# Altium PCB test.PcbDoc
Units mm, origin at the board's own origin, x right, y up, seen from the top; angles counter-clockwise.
Board outline 37.73 x 68.07 mm, 2 copper layers (Top Layer, Bottom Layer); 30 components, 0 nets, 107 pads, 18 vias.
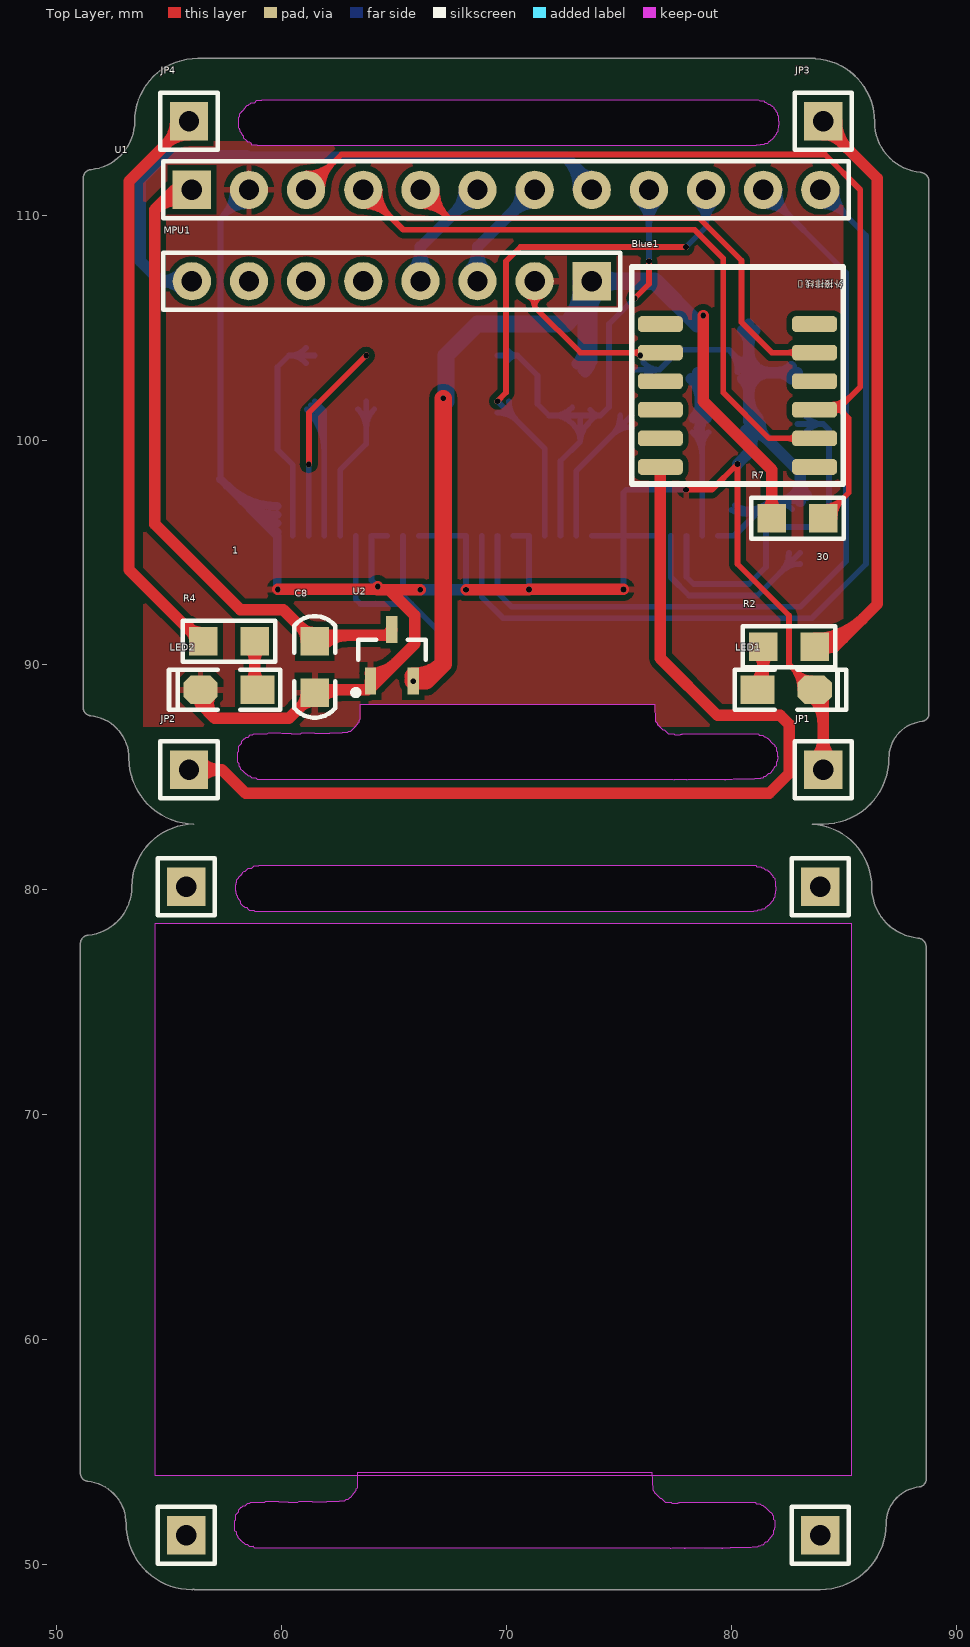
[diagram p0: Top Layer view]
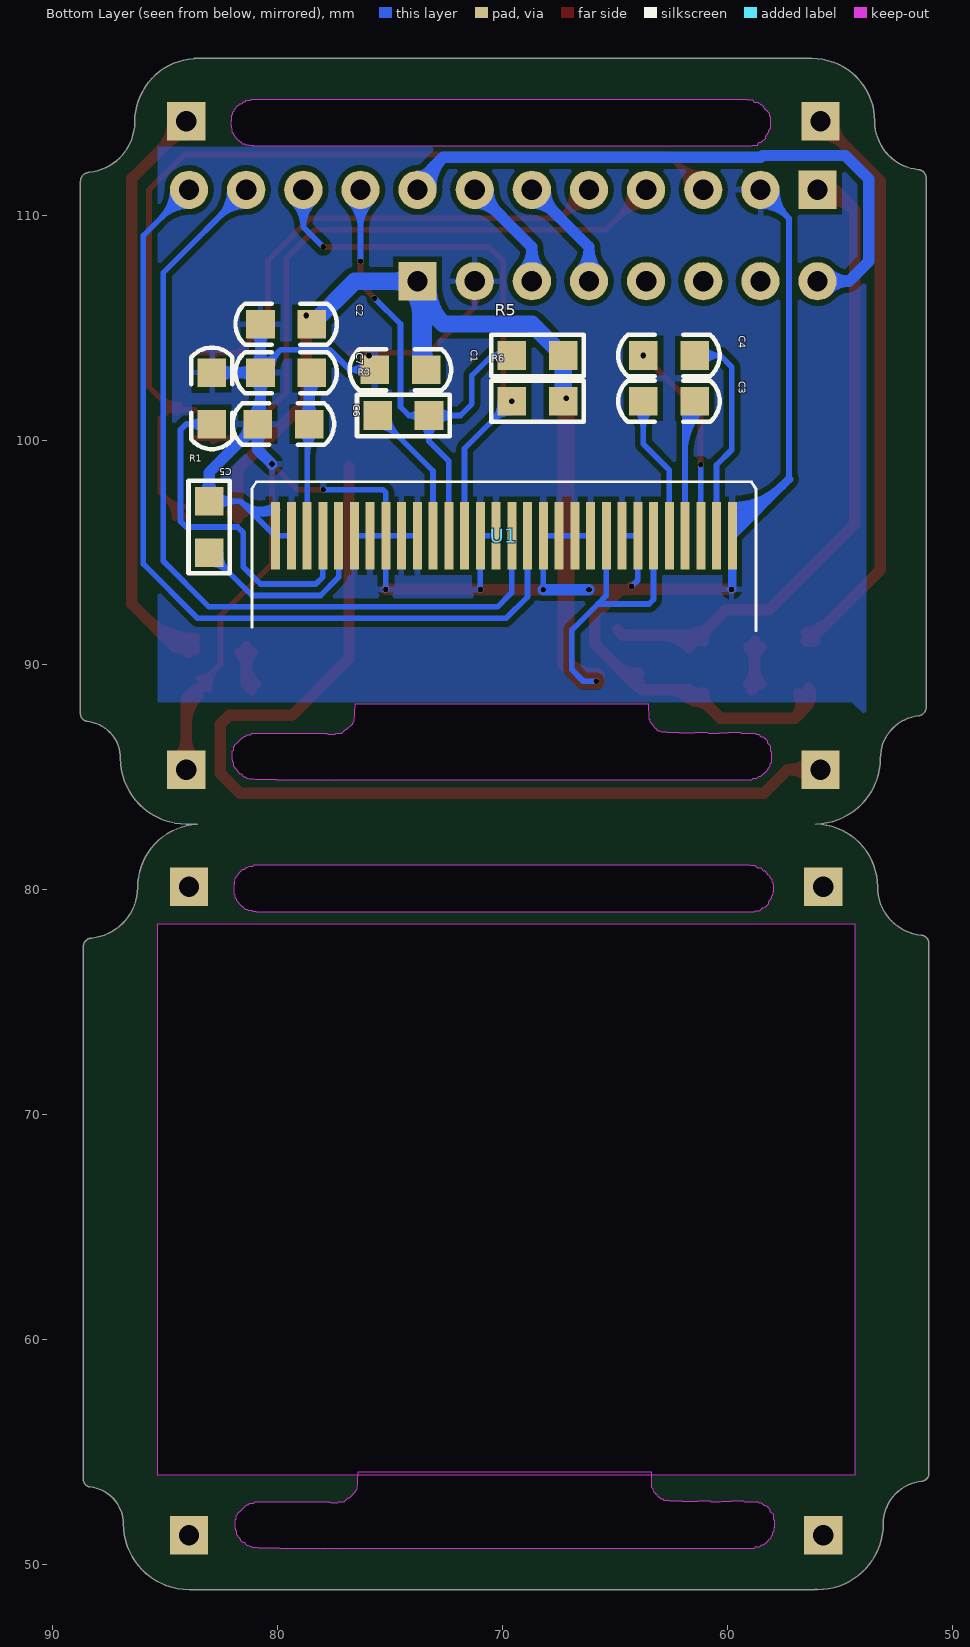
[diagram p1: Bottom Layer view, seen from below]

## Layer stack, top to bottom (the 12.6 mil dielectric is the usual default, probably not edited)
Top Solder: solder mask 0.0102, Solder Resist, Dk 3.5
Top Layer: signal copper 0.0356
Dielectric 1: dielectric 0.32, FR-4, Dk 4.8
Bottom Layer: signal copper 0.0356
Bottom Solder: solder mask 0.0102, Solder Resist, Dk 3.5

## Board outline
51.363,53.712 cw(c51.412,54.07) 51.054,54.11 51.054,77.592 cw(c51.426,77.617) 51.394,77.989 ccw(c51.181,80.137) 53.34,80.137 cw(c56.134,80.137) 56.087,82.931 cw(c56.134,85.852) 53.213,85.852 cw(c53.34,85.852) 53.213,85.853 cw(c51.308,85.852) 53.213,85.852 53.213,85.853 ccw(c51.308,85.852) 51.496,87.747 ccw(c51.308,85.852) 51.495,87.747 51.496,87.747 cw(c51.507,87.874) 51.49,87.748 cw(c51.539,88.106) 51.181,88.146 51.181,111.628 cw(c51.553,111.653) 51.521,112.025 ccw(c51.308,114.173) 53.467,114.173 cw(c56.261,114.173) 56.261,116.967 83.693,116.967 cw(c83.693,116.84) 83.732,116.961 cw(c83.545,114.152) 86.36,114.152 cw(c83.545,114.152) 86.36,114.131 cw(c88.625,114.152) 86.36,114.132 86.36,114.131 ccw(c88.625,114.152) 88.398,111.899 cw(c88.386,111.511) 88.773,111.511 cw(c88.386,111.511) 88.773,111.505 cw(c88.386,111.511) 88.773,111.504 88.773,111.506 88.773,87.895 cw(c88.428,87.84) 88.778,87.84 cw(c88.428,87.84) 88.497,87.497 cw(c88.472,87.621) 88.482,87.494 cw(c88.646,85.852) 88.484,87.495 88.482,87.494 ccw(c88.646,85.852) 86.995,85.852 cw(c84.074,85.852) 84.074,82.931 83.58,82.931 cw(c83.566,82.804) 83.605,82.925 cw(c83.418,80.116) 86.233,80.116 cw(c83.418,80.116) 86.233,80.095 cw(c88.498,80.116) 86.233,80.096 86.233,80.095 ccw(c88.498,80.116) 88.271,77.863 cw(c88.259,77.475) 88.646,77.475 cw(c88.259,77.475) 88.646,77.469 cw(c88.259,77.475) 88.646,77.468 88.646,77.47 88.646,53.859 cw(c88.301,53.804) 88.651,53.804 cw(c88.301,53.804) 88.37,53.461 cw(c88.345,53.585) 88.355,53.458 cw(c88.519,51.816) 88.357,53.459 88.355,53.458 ccw(c88.519,51.816) 86.868,51.816 cw(c83.947,51.816) 83.947,48.895 56.142,48.895 cw(c56.142,49.022) 56.074,48.914 cw(c56.007,49.022) 56.007,48.895 cw(c56.007,51.816) 53.086,51.816 cw(c53.213,51.816) 53.086,51.817 cw(c51.181,51.816) 53.086,51.816 53.086,51.817 ccw(c51.181,51.816) 51.369,53.711 cw(c51.38,53.838)
cut-out: 58.01,80.46 58.1,80.55 58.1,80.58 58.11,80.58 58.21,80.68 58.22,80.68 58.22,80.7 58.28,80.76 58.28,80.78 58.34,80.84 58.39,80.84 58.52,80.97 58.67,80.97 58.77,81.07 58.98,81.07 59.01,81.1 81.07,81.1 81.13,81.04 81.3,81.04 81.35,80.99 81.4,80.99 81.5,80.89 81.58,80.89 81.64,80.83 81.66,80.83 81.74,80.75 81.74,80.72 81.83,80.63 81.83,80.59 81.91,80.51 81.91,80.42 81.94,80.39 81.94,80.26 81.95,80.25 81.95,80.16 81.97,80.14 81.97,79.96 81.95,79.94 81.95,79.84 81.92,79.81 81.92,79.67 81.86,79.61 81.86,79.55 81.74,79.43 81.74,79.4 81.63,79.29 81.61,79.29 81.54,79.22 81.53,79.22 81.45,79.14 81.35,79.14 81.31,79.1 81.16,79.1 81.12,79.06 80.98,79.06 80.96,79.04 58.82,79.04 58.78,79.08 58.57,79.08 58.51,79.14 58.51,79.15 58.46,79.2 58.39,79.2 58.33,79.26 58.31,79.26 58.18,79.39 58.18,79.47 58.16,79.49 58.15,79.49 58.15,79.52 58.09,79.58 58.09,79.61 58.04,79.66 58.04,79.73 58.01,79.76 58.01,79.77 58,79.78 58,79.8 57.97,79.83 57.97,79.94 57.96,79.95 57.96,80.24 57.97,80.25 57.97,80.31 58.01,80.35
cut-out: 63.373,54.102 76.454,54.102 76.488,53.325 76.572,53.241 76.572,53.191 76.592,53.191 76.822,52.961 76.882,52.961 77.062,52.781 77.312,52.781 77.352,52.741 77.602,52.741 77.622,52.761 77.672,52.761 77.682,52.771 81.052,52.771 81.102,52.721 81.262,52.721 81.332,52.651 81.382,52.651 81.462,52.571 81.482,52.571 81.712,52.341 81.732,52.341 81.732,52.331 81.802,52.261 81.802,52.231 81.862,52.171 81.862,52.021 81.912,51.971 81.912,51.791 81.922,51.781 81.922,51.641 81.902,51.621 81.902,51.561 81.852,51.511 81.852,51.361 81.782,51.291 81.782,51.261 81.702,51.181 81.702,51.151 81.642,51.091 81.642,51.071 81.562,50.991 81.502,50.991 81.382,50.871 81.312,50.871 81.252,50.811 81.182,50.811 81.152,50.781 80.912,50.781 80.882,50.751 80.062,50.751 80.052,50.761 79.942,50.761 79.912,50.731 79.602,50.731 79.592,50.721 79.582,50.731 78.982,50.731 78.972,50.741 78.752,50.741 78.742,50.731 77.922,50.731 77.912,50.721 77.892,50.741 77.332,50.741 77.302,50.711 77.282,50.731 58.812,50.731 58.732,50.811 58.712,50.791 58.572,50.791 58.482,50.881 58.402,50.881 58.312,50.971 58.292,50.971 58.292,50.981 58.202,51.071 58.192,51.071 58.192,51.081 58.062,51.211 58.062,51.251 58.042,51.271 58.042,51.291 57.992,51.341 57.992,51.441 57.922,51.511 57.922,51.661 57.912,51.671 57.912,51.961 57.962,52.011 57.962,52.221 58.102,52.361 58.102,52.441 58.192,52.531 58.192,52.551 58.222,52.551 58.302,52.631 58.382,52.631 58.482,52.731 58.592,52.731 58.632,52.771 59.242,52.771 59.292,52.821 59.542,52.821 59.552,52.831 59.842,52.831 59.872,52.801 60.272,52.801 60.302,52.771 60.722,52.771 60.772,52.821 61.332,52.821 61.352,52.801 62.012,52.801 62.032,52.821 62.372,52.821 62.382,52.831 62.562,52.831 62.582,52.851 62.812,52.851 62.862,52.901 62.952,52.901 63.052,53.001 63.062,53.001 63.062,53.011 63.182,53.131 63.192,53.131 63.192,53.151 63.282,53.241 63.282,53.271 63.312,53.301 63.312,53.371 63.372,53.431 63.372,53.501
cut-out: 54.356,78.486 54.356,53.975 85.344,53.975 85.344,78.486
cut-out: 58.137,114.496 58.227,114.586 58.227,114.616 58.237,114.616 58.337,114.716 58.347,114.716 58.347,114.736 58.407,114.796 58.407,114.816 58.467,114.876 58.517,114.876 58.647,115.006 58.797,115.006 58.897,115.106 59.107,115.106 59.137,115.136 81.197,115.136 81.257,115.076 81.427,115.076 81.477,115.026 81.527,115.026 81.627,114.926 81.707,114.926 81.767,114.866 81.787,114.866 81.867,114.786 81.867,114.756 81.957,114.666 81.957,114.626 82.037,114.546 82.037,114.456 82.067,114.426 82.067,114.296 82.077,114.286 82.077,114.196 82.097,114.176 82.097,113.996 82.077,113.976 82.077,113.876 82.047,113.846 82.047,113.706 81.987,113.646 81.987,113.586 81.867,113.466 81.867,113.436 81.757,113.326 81.737,113.326 81.667,113.256 81.657,113.256 81.577,113.176 81.477,113.176 81.437,113.136 81.287,113.136 81.247,113.096 81.107,113.096 81.087,113.076 58.947,113.076 58.907,113.116 58.697,113.116 58.637,113.176 58.637,113.186 58.587,113.236 58.517,113.236 58.457,113.296 58.437,113.296 58.307,113.426 58.307,113.506 58.287,113.526 58.277,113.526 58.277,113.556 58.217,113.616 58.217,113.646 58.167,113.696 58.167,113.766 58.137,113.796 58.137,113.806 58.127,113.816 58.127,113.836 58.097,113.866 58.097,113.976 58.087,113.986 58.087,114.276 58.097,114.286 58.097,114.346 58.137,114.386
cut-out: 63.5,88.265 76.581,88.265 76.615,87.488 76.699,87.404 76.699,87.354 76.719,87.354 76.949,87.124 77.009,87.124 77.189,86.944 77.439,86.944 77.479,86.904 77.729,86.904 77.749,86.924 77.799,86.924 77.809,86.934 81.179,86.934 81.229,86.884 81.389,86.884 81.459,86.814 81.509,86.814 81.589,86.734 81.609,86.734 81.839,86.504 81.859,86.504 81.859,86.494 81.929,86.424 81.929,86.394 81.989,86.334 81.989,86.184 82.039,86.134 82.039,85.954 82.049,85.944 82.049,85.804 82.029,85.784 82.029,85.724 81.979,85.674 81.979,85.524 81.909,85.454 81.909,85.424 81.829,85.344 81.829,85.314 81.769,85.254 81.769,85.234 81.689,85.154 81.629,85.154 81.509,85.034 81.439,85.034 81.379,84.974 81.309,84.974 81.279,84.944 81.039,84.944 81.009,84.914 80.189,84.914 80.179,84.924 80.069,84.924 80.039,84.894 79.729,84.894 79.719,84.884 79.709,84.894 79.109,84.894 79.099,84.904 78.879,84.904 78.869,84.894 78.049,84.894 78.039,84.884 78.019,84.904 77.459,84.904 77.429,84.874 77.409,84.894 58.939,84.894 58.859,84.974 58.839,84.954 58.699,84.954 58.609,85.044 58.529,85.044 58.439,85.134 58.419,85.134 58.419,85.144 58.329,85.234 58.319,85.234 58.319,85.244 58.189,85.374 58.189,85.414 58.169,85.434 58.169,85.454 58.119,85.504 58.119,85.604 58.049,85.674 58.049,85.824 58.039,85.834 58.039,86.124 58.089,86.174 58.089,86.384 58.229,86.524 58.229,86.604 58.319,86.694 58.319,86.714 58.349,86.714 58.429,86.794 58.509,86.794 58.609,86.894 58.719,86.894 58.759,86.934 59.369,86.934 59.419,86.984 59.669,86.984 59.679,86.994 59.969,86.994 59.999,86.964 60.399,86.964 60.429,86.934 60.849,86.934 60.899,86.984 61.459,86.984 61.479,86.964 62.139,86.964 62.159,86.984 62.499,86.984 62.509,86.994 62.689,86.994 62.709,87.014 62.939,87.014 62.989,87.064 63.079,87.064 63.179,87.164 63.189,87.164 63.189,87.174 63.309,87.294 63.319,87.294 63.319,87.314 63.409,87.404 63.409,87.434 63.439,87.464 63.439,87.534 63.499,87.594 63.499,87.664

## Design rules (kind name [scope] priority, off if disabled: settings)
Clearance [All] p1: gap=0.254
PolygonConnect [All] p1: connectstyle=Relief reliefconductorwidth=0.254 reliefentries=4 polygonreliefangle="90 Angle" airgapwidth=0.254
RoutingVias [All] p1: holewidth=0.711 width=1.27 viastyle="Through Hole" minholewidth=0.711 minwidth=1.27 maxholewidth=0.711 maxwidth=1.27
SolderMaskExpansion [All] p1: expansion=0.102
Width [All] p1: maxlimit=0.254 minlimit=0.254 preferedwidth=0.254
29 further rules are at their usual default settings.

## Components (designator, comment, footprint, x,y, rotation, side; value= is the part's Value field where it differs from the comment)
Blue1 "蓝牙5.0模块" PW02 76.835,103.886 r0 top
C1 "105" "C 0805" 74.549,103.124 r180 bottom
C2 "225" "C 0805" 79.629,105.156 r180 bottom
C3 "105" "C 0805" 62.611,101.727 r180 bottom
C4 "105" "C 0805" 62.611,103.759 r180 bottom
C5 "225" "C 0805" 82.931,101.854 r270 bottom
C6 "225" "C 0805" 79.756,100.711 r180 bottom
C7 "105" "C 0805" 79.629,102.997 r180 bottom
C8 "105" "C 0805" 61.468,89.916 r270 top
JP1 "HDR-1X1" HDR-1X1 83.947,51.308 r0 top
JP1 "HDR-1X1" HDR-1X1 84.074,85.344 r0 top
JP2 "HDR-1X1" HDR-1X1 55.753,51.308 r0 top
JP2 "HDR-1X1" HDR-1X1 55.88,85.344 r0 top
JP3 "HDR-1X1" HDR-1X1 83.947,80.137 r0 top
JP3 "HDR-1X1" HDR-1X1 84.074,114.173 r0 top
JP4 "HDR-1X1" HDR-1X1 55.753,80.137 r0 top
JP4 "HDR-1X1" HDR-1X1 55.88,114.173 r0 top
LED1 "红色" "LED 0805B" 82.423,88.9 r0 top
LED2 "红色" "LED 0805G" 57.658,88.9 r180 top
MPU1 "HDR-1X8" HDR-1X8 73.787,107.061 r180 top
R1 "560K" "R 0805" 83.058,96.139 r270 bottom
R2 "1K" "R 0805" 82.55,90.805 r0 top
R3 "0R" "R 0805" 74.422,101.092 r0 bottom
R4 "1K" "R 0805" 57.658,91.059 r180 top
R5 "4.7K" "R 0805" 68.453,103.759 r180 bottom
R6 "4.7K" "R 0805" 68.453,101.727 r180 bottom
R7 "10K" "R 0805" 82.931,96.52 r180 top
U1 "1.3寸OLED，PFC线30pin" 1.3寸OLED-PFC 69.85,93.091 r0 top
U2 "XC6206" SOT23-3N 64.897,90.424 r0 top
外接排线1 "HDR-1X12" HDR-1X12 56.007,111.125 r0 top

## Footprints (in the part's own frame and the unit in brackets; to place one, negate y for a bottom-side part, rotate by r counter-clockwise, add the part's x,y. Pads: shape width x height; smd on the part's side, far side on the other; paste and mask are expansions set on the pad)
1.3寸OLED-PFC [mm] "用于OLED的30针脚"
  rect 0.4x3 smd far side: 1(-10.052,2.654) 2(-9.352,2.654) 3(-8.652,2.654) 4(-7.952,2.654) 5(-7.252,2.654) 6(-6.552,2.654) 7(-5.852,2.654) 8(-5.152,2.654) 9(-4.452,2.654) 10(-3.752,2.654) 11(-3.052,2.654) 12(-2.352,2.654) 13(-1.652,2.654) 14(-0.952,2.654) 15(-0.252,2.654) 16(0.448,2.654) 17(1.148,2.654) 18(1.848,2.654) 19(2.548,2.654) 20(3.248,2.654) 21(3.948,2.654) 22(4.648,2.654) 23(5.348,2.654) 24(6.048,2.654) 25(6.748,2.654) 26(7.448,2.654) 27(8.148,2.654) 28(8.848,2.654) 29(9.548,2.654) 30(10.248,2.654)
  body extent -17.4,-4.95 17.6,18.91, height 2.44
"C 0805" [mil] "无极性贴片电容"
  rect 50x50 smd: 1(-45,0) 2(45,0)
  silkscreen extent -89,-36 89,36, body extent -39,-24 39,24, height 20
HDR-1X1 [mm] "排针，1脚"
  rect 1.7x1.7 hole 0.9: 1(0,0)
  silkscreen extent -1.27,-1.27 1.27,1.27, body extent -1.27,-1.27 1.27,1.27, height 8.5
HDR-1X8 [mm] "排针，8脚"
  rect 1.7x1.7 hole 0.9: 1(0,0)
  round 1.7 hole 0.9: 2(2.54,0) 3(5.08,0) 4(7.62,0) 5(10.16,0) 6(12.7,0) 7(15.24,0) 8(17.78,0)
  silkscreen extent -1.27,-1.27 19.05,1.27, body extent -1.27,-1.27 19.05,1.27, height 8.5
HDR-1X12 [mm] "排针，13脚"
  rect 1.7x1.7 hole 0.9: 1(0,0)
  round 1.7 hole 0.9: 2(2.54,0) 3(5.08,0) 4(7.62,0) 5(10.16,0) 6(12.7,0) 7(15.24,0) 8(17.78,0) 9(20.32,0) 10(22.86,0) 11(25.4,0) 12(27.94,0)
  silkscreen extent -1.27,-1.27 29.21,1.27, body extent -1.27,-1.27 29.21,1.27, height 8.5
"LED 0805B" [mil] "蓝色0805LED"
  rect 60x50 smd: 1(-50,0)
  oct 60x50 smd: 2(50,0)
  silkscreen extent -90,-35 105,35, body extent -39,-25 39,25, height 32
"LED 0805G" [mil] "绿色0805LED"
  rect 60x50 smd: 1(-50,0)
  oct 60x50 smd: 2(50,0)
  silkscreen extent -90,-35 105,35, body extent -39,-25 39,25, height 32
PW02 [mm] "蓝牙5.0模块"
  rrect50% 2x0.7 / inner round 0 / far side round 0 all layers, no hole: 1(0,1.27) 2(0,0) 3(0,-1.27) 4(0,-2.54) 5(0,-3.81) 6(0,-5.08) 7(6.858,-5.08) 8(6.858,-3.81) 9(6.858,-2.54) 10(6.858,-1.27) 11(6.858,0) 12(6.858,1.27)
  silkscreen extent -1.27,-5.84 8.13,3.81
"R 0805" [mil] "1/8W贴片电阻"
  rect 50x50 smd: 1(-45,0) 2(45,0)
  silkscreen extent -81,-36 81,36, body extent -39,-25 39,25, height 20
SOT23-3N [mm] "3x1.3x1mm(长宽高)"
  rect 0.5x1.2 smd: 1(-0.95,-1.143) 2(0.95,-1.143) 3(0,1.143)
  silkscreen extent -1.72,-1.78 1.5,0.7, body extent -1.5,-1.2 1.5,1.2, height 1.05

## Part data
Blue1: library part PW02
C1 C2 C3 C4 C5 C6 C7 C8: library part C, "无极性贴片电容"
JP1 JP1 JP2 JP2 JP3 JP3 JP4 JP4: library part "Header 1", "1P接插件"
LED1 LED2: library part LED-SMD, "贴片LED"
MPU1: library part "Header 8", "8P接插件"
R1 R2 R3 R4 R5 R6 R7: library part R, "贴片电阻"
U2: "稳压芯片"
外接排线1: library part "Header 12", "12P接插件"

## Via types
v1: diameter 0.254, hole 0.254, Top Layer to Bottom Layer, 18 vias

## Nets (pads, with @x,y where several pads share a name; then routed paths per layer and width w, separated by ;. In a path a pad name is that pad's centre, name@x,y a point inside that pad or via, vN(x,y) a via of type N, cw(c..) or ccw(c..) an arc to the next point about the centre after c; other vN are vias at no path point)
pads on no net: Blue1.1 Blue1.2 Blue1.3 Blue1.4 Blue1.5 Blue1.6 Blue1.7 Blue1.8 Blue1.9 Blue1.10 Blue1.11 Blue1.12 C1.1 C1.2 C2.1 C2.2 C3.1 C3.2 C4.1 C4.2 C5.1 C5.2 C6.1 C6.2 C7.1 C7.2 C8.1 C8.2 JP1.1 JP2.1 JP3.1 JP4.1 LED1.1 LED1.2 LED2.1 LED2.2 MPU1.1 MPU1.2 MPU1.3 MPU1.4 MPU1.5 MPU1.6 MPU1.7 MPU1.8 R1.1 R1.2 R2.1 R2.2 R3.1 R3.2 R4.1 R4.2 R5.1 R5.2 R6.1 R6.2 R7.1 R7.2 U1.1 U1.2 U1.3 U1.4 U1.5 U1.6 U1.7 U1.8 U1.9 U1.10 U1.11 U1.12 U1.13 U1.14 U1.15 U1.16 U1.17 U1.18 U1.19 U1.20 U1.21 U1.22 U1.23 U1.24 U1.25 U1.26 U1.27 U1.28 U1.29 U1.30 U2.1 U2.2 U2.3 外接排线1.1 外接排线1.2 外接排线1.3 外接排线1.4 外接排线1.5 外接排线1.6 外接排线1.7 外接排线1.8 外接排线1.9 外接排线1.10 外接排线1.11 外接排线1.12
copper on no net: | length 798.5
  Top Layer w0.254: 61.087,111.125 62.657,112.695 84.155,112.695 85.725,111.125 85.725,102.362 84.709,101.346 ; 61.087,111.594 ccw(c61.087,112.726) 61.888,111.926 ccw(c62.688,111.125) 61.556,111.125 ; 61.087,111.848 ccw(c61.087,113.593) 62.321,112.359 ccw(c63.555,111.125) 61.81,111.125 ; v1@61.214,98.933 61.214,101.219 v1(63.754,103.759) ; 63.627,110.402 cw(c63.627,108.657) 64.861,109.891 cw(c66.095,111.125) 64.35,111.125 ; 63.627,110.656 cw(c63.627,109.524) 64.428,110.324 cw(c65.228,111.125) 64.096,111.125 ; 63.881,111.125 63.627,111.125 65.405,109.347 78.359,109.347 79.629,108.077 79.629,102.108 81.661,100.076 83.693,100.076 ; 66.167,110.402 cw(c66.167,108.657) 67.401,109.891 cw(c68.635,111.125) 66.89,111.125 ; 66.167,110.656 cw(c66.167,109.524) 66.968,110.324 cw(c67.768,111.125) 66.636,111.125 ; 66.167,111.125 67.437,109.855 78.569,109.855 80.441,107.984 80.441,105.233 81.788,103.886 83.693,103.886 ; v1(69.596,101.727) 69.977,102.108 69.977,107.95 70.612,108.585 v1(77.978,108.585) ; 70.937,106.408 cw(c70.705,105.918) 71.247,105.918 ; 71.247,107.061 71.247,105.918 ; 71.557,106.408 ccw(c71.789,105.918) 71.247,105.918 ; 75.639,103.886 cw(c75.639,103.452) v1(75.946,103.759) cw(c76.253,103.452) 76.253,103.886 ; v1(75.692,106.299) 76.327,106.934 v1(76.327,107.95) ; v1@76.027,103.728 ccw(c75.647,103.348) 75.647,103.886 ccw(c75.647,104.424) 76.027,104.044 ; 76.835,103.886 73.279,103.886 71.247,105.918 ; v1(77.978,97.79) 79.121,97.79 v1(80.264,98.933) 80.264,94.488 82.55,92.202 82.55,90.043 83.693,88.9 ; 82.609,89.984 cw(c81.525,88.9) 83.058,88.9 ; 82.885,99.918 ccw(c82.505,99.538) 82.505,100.076 ccw(c82.505,100.614) 82.885,100.234 ; 82.885,103.728 ccw(c82.505,103.348) 82.505,103.886 ccw(c82.505,104.424) 82.885,104.044 ; 82.916,89.677 ccw(c83.566,90.328) 83.566,89.408 ; 83.043,89.55 cw(c82.392,88.9) 83.312,88.9 ; 83.693,101.346 84.709,101.346 ; 84.074,96.52 85.217,97.663 85.217,100.965 84.836,101.346 ; 84.074,97.028 ccw(c84.074,98.254) 84.941,97.387 ccw(c85.808,96.52) 84.582,96.52 ; 84.343,101.315 ccw(c84.343,102.124) 84.915,101.552 ; 84.343,101.569 ccw(c84.343,102.991) 85.348,101.985 ; 84.51,101.199 cw(c84.836,100.913) 84.836,101.346 ; 84.51,101.493 ccw(c84.836,101.779) 84.836,101.346 ; 84.709,101.346 ccw(c84.709,101.157) 84.541,101.244 cw(c84.709,101.157) 84.709,101.346 ; 84.709,101.346 cw(c84.709,101.535) 84.541,101.448 ccw(c84.709,101.535) 84.709,101.346 ; 84.709,101.346 84.836,101.346
  Top Layer w0.508: 54.925,110.805 cw(c55.639,110.09) 55.978,111.042 ; 55.284,114.173 cw(c53.845,114.173) 54.863,113.156 cw(c55.88,112.138) 55.88,113.577 ; 55.648,91.799 ccw(c56.515,92.666) 56.515,91.44 ; 55.807,110.563 ccw(c55.341,109.251) 54.356,110.236 ; 55.88,85.344 57.344,85.344 58.399,84.289 81.669,84.289 82.557,85.177 82.557,87.365 82.165,87.757 79.375,87.757 76.835,90.297 76.835,98.806 ; 55.88,91.694 56.515,91.059 56.388,91.059 53.213,94.234 53.213,111.506 55.88,114.173 ; 55.954,91.493 cw(c55.521,91.059) 56.134,91.059 ; 56.007,111.125 55.245,111.125 54.356,110.236 ; 56.301,84.923 cw(c57.319,83.905) 57.319,85.344 cw(c57.319,86.783) 56.301,85.765 ; 56.388,88.9 56.388,88.265 57.023,87.63 ; 56.402,88.958 ccw(c57.039,88.628) 56.532,88.121 ; 56.853,88.725 ccw(c57.686,88.293) 57.023,87.63 ; 58.532,89.169 ccw(c57.881,89.82) 58.801,89.82 ccw(c59.721,89.82) 59.07,89.169 ; 58.532,90.79 cw(c57.881,90.139) 58.801,90.139 cw(c59.721,90.139) 59.07,90.79 ; 58.801,91.059 58.801,89.027 58.928,88.9 ; v1(59.831,93.359) 64.149,93.359 v1(64.276,93.486) ; 61.087,88.773 cw(c60.167,88.773) 60.818,88.123 cw(c61.468,87.472) 61.468,88.392 ; 61.087,91.059 ccw(c60.167,91.059) 60.818,91.709 ccw(c61.468,92.36) 61.468,91.44 ; 61.468,88.773 60.325,87.63 57.023,87.63 ; 61.722,88.9 63.82,88.9 63.947,89.027 64.008,89.027 64.262,89.281 ; 61.737,88.504 cw(c62.694,87.547) 62.694,88.9 ; 61.737,90.79 cw(c63.001,89.526) 63.001,91.313 ; 63.947,89.119 ccw(c63.947,89.488) 64.208,89.227 ; 63.947,89.281 64.262,89.281 ; 63.947,89.627 ccw(c63.947,91.223) 65.075,90.094 ; 64.417,93.345 64.77,93.345 ; 64.897,91.567 64.643,91.313 61.722,91.313 61.468,91.059 60.071,92.456 58.166,92.456 54.356,96.266 54.356,110.236 ; v1(66.167,93.345) 64.77,93.345 ; v1(68.199,93.345) 70.979,93.345 v1(70.993,93.359) v1(75.198,93.359) ; v1(78.74,105.537) 78.74,101.727 81.788,98.679 81.788,96.52 ; 81.011,89.169 ccw(c80.054,90.126) 81.407,90.126 ; 81.138,90.536 cw(c80.487,89.885) 81.407,89.885 cw(c82.327,89.885) 81.676,90.536 ; 81.153,88.9 81.407,89.154 81.407,90.805 ; 81.519,96.789 ccw(c80.868,97.44) 81.788,97.44 ccw(c82.708,97.44) 82.057,96.789 ; 83.551,88.631 cw(c82.287,87.367) 84.074,87.367 ; 83.653,85.765 ccw(c82.635,86.783) 84.074,86.783 ccw(c85.513,86.783) 84.495,85.765 ; 83.693,88.9 84.074,88.519 84.074,85.344 ; 83.693,90.678 ccw(c83.693,92.518) 84.994,91.217 ; 83.693,90.805 84.582,90.805 ; 83.693,91.186 ccw(c83.693,94.252) 85.861,92.084 ; 83.969,90.542 cw(c84.582,89.958) 84.582,90.805 ; 83.969,91.068 ccw(c84.582,91.652) 84.582,90.805 ; 84.074,113.577 cw(c84.074,112.445) 84.875,113.245 ; 84.074,114.173 84.074,114.046 86.487,111.633 86.487,92.71 84.582,90.805 ; 84.67,114.173 ccw(c86.415,114.173) 85.181,112.939 ; 64.262,89.281 65.913,90.932 65.913,92.202 64.77,93.345 ; 64.186,93.396 ccw(c64.31,93.52) 64.31,93.345 cw(c64.31,93.52) 64.186,93.396
  Top Layer w0.762: 65.845,89.5 ccw(c65.872,91.354) 67.183,90.043 ; v1(65.847,89.281) 66.421,89.281 67.183,90.043 ; v1(67.183,101.854) 67.183,90.043
  Bottom Layer w0.254: 57.277,98.266 57.277,109.855 58.547,111.125 ; 57.824,111.125 cw(c56.079,111.125) 57.313,109.891 cw(c58.547,108.657) 58.547,110.402 ; 58.078,111.125 cw(c56.946,111.125) 57.746,110.324 cw(c58.547,109.524) 58.547,110.656 ; 60.498,95.745 60.498,98.887 59.817,99.568 59.817,103.251 60.325,103.759 ; 61.091,103.419 ccw(c60.325,102.727) 60.325,103.759 ; 61.091,104.099 cw(c60.325,104.791) 60.325,103.759 ; 61.109,101.368 cw(c59.203,99.462) 61.898,99.462 ; 61.198,95.745 v1(61.198,98.917) ; 61.288,101.547 cw(c59.817,100.076) 61.898,100.076 ; 61.468,103.759 60.325,103.759 ; 61.898,95.745 61.898,101.297 61.468,101.727 cw(c60.43,100.689) 61.898,100.689 ; 62.598,95.745 62.598,98.666 63.754,99.822 63.754,101.727 ; 63.298,95.745 63.298,92.912 63.5,92.71 65.772,92.71 ; 63.395,101.368 cw(c62.528,100.501) 63.754,100.501 cw(c64.98,100.501) 64.113,101.368 ; v1(64.276,93.486) 63.998,93.764 63.998,95.745 64.698,95.745 ; 65.398,95.745 65.398,93.084 65.772,92.71 ; v1(65.847,89.281) 66.421,89.281 66.929,89.789 66.929,91.553 65.772,92.71 ; 66.098,95.745 66.798,95.745 67.498,95.745 68.198,95.745 v1(68.199,93.345) v1(68.199,93.345) ; 68.898,95.745 68.898,93.027 69.85,92.075 83.566,92.075 85.979,94.488 85.979,109.093 83.947,111.125 ; 69.596,101.219 cw(c69.596,99.993) 70.463,100.86 cw(c71.33,101.727) 70.104,101.727 ; v1(69.596,101.727) 71.698,99.625 71.698,95.745 ; 69.596,103.759 70.485,103.759 ; 69.598,95.745 69.598,93.216 70.231,92.583 83.058,92.583 85.09,94.615 85.09,107.442 81.407,111.125 81.407,110.49 ; 70.034,103.501 cw(c70.485,103.235) 70.485,103.759 ; 70.034,104.017 ccw(c70.485,104.283) 70.485,103.759 ; 70.298,95.745 70.998,95.745 70.998,93.364 v1(70.993,93.359) ; 72.398,95.745 72.398,99.068 73.279,99.949 ; 72.92,100.733 ccw(c72.053,99.866) 72.053,101.092 ccw(c72.053,102.318) 72.92,101.451 ; 72.939,100.715 cw(c72.247,99.949) 73.279,99.949 ; 73.098,95.745 73.098,98.625 75.565,101.092 ; 73.619,100.715 ccw(c74.311,99.949) 73.279,99.949 ; 73.717,100.834 cw(c74.168,100.568) 74.168,101.092 ; 73.717,101.35 ccw(c74.168,101.616) 74.168,101.092 ; 73.798,95.745 74.498,95.745 75.198,95.745 ; 75.057,101.092 cw(c73.831,101.092) 74.698,100.225 cw(c75.565,99.358) 75.565,100.584 ; v1(75.198,93.359) 75.198,95.745 ; 75.692,103.124 76.804,103.124 ; v1(75.692,106.299) 74.549,105.156 74.549,101.473 74.168,101.092 ; 75.816,110.614 cw(c74.582,109.38) 76.327,109.38 cw(c78.072,109.38) 76.838,110.614 ; 75.995,110.793 cw(c75.195,109.993) 76.327,109.993 cw(c77.459,109.993) 76.659,110.793 ; 76.076,102.791 cw(c76.804,102.161) 76.804,103.124 ; 76.076,103.457 ccw(c76.804,104.087) 76.804,103.124 ; v1(76.327,107.95) 76.327,111.125 ; 76.598,95.745 75.898,95.745 75.198,95.745 ; 77.298,95.745 77.298,93.898 78.105,93.091 81.153,93.091 83.058,94.996 ; v1(77.978,97.79) 75.325,97.79 75.198,97.663 75.198,95.745 ; v1(77.978,108.585) 78.867,109.474 ; 77.998,95.745 77.998,93.916 78.315,93.599 80.772,93.599 81.534,94.361 81.534,95.885 81.788,96.139 84.074,96.139 84.328,96.393 84.328,100.457 84.074,100.711 ; 78.254,100.352 cw(c77.181,99.279) 78.698,99.279 ; 78.377,110.594 cw(c77.344,109.474) 78.867,109.474 ; 78.433,100.531 cw(c77.795,99.893) 78.698,99.893 ; 78.549,110.78 cw(c77.879,110.054) 78.867,110.054 cw(c79.855,110.054) 79.185,110.78 ; 78.613,100.711 78.698,100.626 78.698,95.745 ; 78.698,99.69 cw(c79.634,99.69) 78.972,100.352 ; 78.867,111.125 78.867,109.474 ; 79.357,110.594 ccw(c80.39,109.474) 78.867,109.474 ; 79.398,95.745 80.098,95.745 80.124,95.745 81.661,97.282 ; 80.002,96.891 ccw(c80.615,97.876) 81.435,97.056 ; 80.122,103.774 ccw(c80.772,104.425) 80.772,103.505 ; 80.137,97.107 ccw(c80.789,98.154) 81.661,97.282 ; 80.265,103.022 ccw(c78.958,103.088) 79.883,104.013 ; 80.288,103.608 cw(c79.729,103.049) 80.518,103.01 ; 80.772,102.997 80.772,103.124 79.883,104.013 ; 81.407,110.402 cw(c81.407,108.657) 82.641,109.891 cw(c83.875,111.125) 82.13,111.125 ; 81.407,110.656 cw(c81.407,109.524) 82.208,110.324 cw(c83.008,111.125) 81.876,111.125 ; 82.55,94.996 cw(c81.324,94.996) 82.191,94.129 cw(c83.058,93.262) 83.058,94.488 ; 82.699,96.923 ccw(c81.832,96.056) 81.832,97.282 ccw(c81.832,98.508) 82.699,97.641 ; 82.931,100.711 84.074,100.711 ; 83.058,97.282 81.661,97.282 ; 83.308,100.371 cw(c84.074,99.679) 84.074,100.711 ; 83.308,101.051 ccw(c84.074,101.743) 84.074,100.711 ; 83.947,110.402 cw(c83.947,108.657) 85.181,109.891 cw(c86.415,111.125) 84.67,111.125 ; 83.947,110.656 cw(c83.947,109.524) 84.748,110.324 cw(c85.548,111.125) 84.416,111.125 ; 70.485,103.759 71.374,102.87 71.374,101.6 71.882,101.092 73.279,101.092 ; 73.279,99.949 73.279,101.092 ; 73.279,101.092 74.168,101.092 ; 76.804,103.124 77.693,104.013 79.883,104.013
  Bottom Layer w0.381: 57.277,98.266 59.798,95.745 59.798,93.392 v1(59.831,93.359) ; 57.563,97.98 ccw(c59.798,100.216) 59.798,97.054 ; 58.213,97.33 ccw(c59.798,98.915) 59.798,96.673 ; 58.863,96.68 ccw(c59.798,97.614) 59.798,96.292 ; 59.514,96.029 ccw(c59.798,96.313) 59.798,95.911
  Bottom Layer w0.508: 55.577,106.649 ccw(c54.61,105.722) 54.61,107.061 ; 55.577,107.473 cw(c54.61,108.4) 54.61,107.061 ; 56.007,107.061 54.61,107.061 ; 65.746,107.482 ccw(c64.728,108.5) 66.167,108.5 ccw(c67.606,108.5) 66.588,107.482 ; v1(66.167,93.345) v1(68.199,93.345) ; 66.167,107.061 66.167,108.585 68.707,111.125 ; 68.111,111.125 cw(c66.672,111.125) 67.69,110.108 cw(c68.707,109.09) 68.707,110.529 ; 68.286,107.482 ccw(c67.268,108.5) 68.707,108.5 ccw(c70.146,108.5) 69.128,107.482 ; 68.707,107.061 68.707,108.585 71.247,111.125 ; 70.651,111.125 cw(c69.212,111.125) 70.23,110.108 cw(c71.247,109.09) 71.247,110.529 ; 73.192,111.153 ccw(c71.317,111.241) 72.644,112.568 ; 73.282,111.93 ccw(c73.787,112.436) 73.787,111.721 ; 73.366,106.64 cw(c72.348,105.622) 73.787,105.622 cw(c75.226,105.622) 74.208,106.64 ; 73.406,103.124 73.406,105.918 73.406,106.68 73.787,107.061 73.787,103.505 ; 73.406,105.856 cw(c74.041,105.856) 73.91,106.478 ; 73.496,103.034 ccw(c72.793,103.737) 73.787,103.737 ; 73.675,103.393 cw(c74.326,104.044) 73.406,104.044 cw(c72.486,104.044) 73.137,103.393 ccw(c71.566,104.964) 73.787,104.964 ; 73.787,111.125 73.787,111.425 72.644,112.568 ; 78.217,102.728 cw(c77.26,101.771) 78.613,101.771 ; 78.344,100.98 ccw(c77.693,101.631) 78.613,101.631 ccw(c79.533,101.631) 78.882,100.98 ; 78.486,102.997 78.613,102.87 78.613,100.711 ; v1(80.264,98.933) 80.899,99.568 80.899,100.711 ; 80.503,102.728 cw(c79.852,102.077) 80.772,102.077 cw(c81.692,102.077) 81.041,102.728 cw(c81.692,102.077) 81.692,102.997 cw(c81.692,103.917) 81.041,103.266 cw(c81.692,103.917) 80.772,103.917 cw(c79.852,103.917) 80.503,103.266 ; 80.503,104.887 cw(c79.852,104.236) 80.772,104.236 cw(c81.692,104.236) 81.041,104.887 ; 80.63,100.442 cw(c79.979,99.791) 80.899,99.791 cw(c81.819,99.791) 81.168,100.442 ; 80.772,101.937 ccw(c82.125,101.937) 81.168,100.98 ; 80.772,103.124 80.772,105.156 ; 80.899,100.33 cw(c80.899,99.41) 81.549,100.061 cw(c82.2,100.711) 81.28,100.711 ; 82.662,102.728 ccw(c82.011,102.077) 82.011,102.997 ccw(c82.011,103.917) 82.662,103.266 ; 82.789,97.551 ccw(c82.138,98.202) 83.058,98.202 ccw(c83.978,98.202) 83.327,97.551 ; 82.931,102.997 80.772,102.997 80.772,100.838 80.899,100.711 ; 83.058,97.282 83.058,98.552 80.899,100.711 ; 54.61,107.061 53.721,107.95 53.721,111.594 54.776,112.649 58.446,112.649 58.527,112.568 72.644,112.568
  Bottom Layer w0.762: 67.31,101.727 67.31,103.759 68.707,105.156 72.644,105.156 ; 73.32,107.019 cw(c70.99,106.81) 72.644,105.156 ; 73.434,106.752 cw(c72.974,106.35) 73.406,105.918 72.644,105.156 ; 73.787,107.061 76.581,107.061 78.486,105.156 ; 74.119,106.729 cw(c74.919,105.929) 74.919,107.061 cw(c74.919,108.193) 74.119,107.393

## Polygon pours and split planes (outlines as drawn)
no net on Top Layer "Bottom Layer-No Net" (solid, pour order 2): 53.848,87.249 53.848,113.284 85.344,113.284 84.963,112.903 84.963,87.249
no net on Bottom Layer "Bottom Layer-No Net" (solid, pour order 4): 53.848,113.03 53.848,87.757 54.496,88.345 85.344,88.345 85.344,113.03

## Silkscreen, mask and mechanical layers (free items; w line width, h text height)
Mechanical 1:
  lines w0.1: 58.97,79.055 cw(c58.97,80.055) 58.97,81.055 ; 59.097,113.091 cw(c59.097,114.091) 59.097,115.091 ; 63.412,53.703 cw(c62.414,53.771) 62.414,52.771 58.912,52.771 ccw(c58.912,51.771) 58.912,50.771 80.912,50.771 ccw(c80.912,51.771) 80.912,52.771 77.41,52.771 cw(c77.41,53.771) 76.412,53.703 ; 63.539,87.866 cw(c62.541,87.934) 62.541,86.934 59.039,86.934 ccw(c59.039,85.934) 59.039,84.934 81.039,84.934 ccw(c81.039,85.934) 81.039,86.934 77.537,86.934 cw(c77.537,87.934) 76.539,87.866 ; 80.97,79.055 ccw(c80.97,80.055) 80.97,81.055 ; 81.097,113.091 ccw(c81.097,114.091) 81.097,115.091
  lines w0.102: 58.97,79.055 80.975,79.055 ; 59.055,81.055 80.97,81.055 ; 59.097,113.091 81.072,113.091 ; 59.152,115.091 81.097,115.091 ; 63.372,53.501 63.372,53.974 ; 63.499,87.664 63.499,88.137 ; 63.5,88.265 76.581,88.265 76.539,88.223 76.539,88.096 76.539,87.866 ; 66.166,88.137 66.166,88.264 66.167,88.265 ; 76.412,53.703 76.412,53.933
  lines w0.254: 56.007,49.022 cw(c56.007,51.816) 53.213,51.816 ccw(c51.181,51.816) 51.38,53.838 cw(c51.412,54.07) 51.181,54.102 51.181,77.597 cw(c51.426,77.617) 51.405,77.862 ccw(c51.181,80.137) 53.467,80.137 cw(c56.134,80.137) 56.134,82.804 56.134,83.058 cw(c56.134,85.852) 53.34,85.852 ccw(c51.308,85.852) 51.507,87.874 cw(c51.539,88.106) 51.308,88.138 51.308,111.633 cw(c51.553,111.653) 51.532,111.898 ccw(c51.308,114.173) 53.594,114.173 cw(c56.261,114.173) 56.261,116.84 83.693,116.84 ; 56.142,49.022 83.947,49.022 ccw(c83.947,51.816) 86.741,51.816 cw(c88.519,51.816) 88.345,53.585 ccw(c88.301,53.804) 88.519,53.848 88.519,77.47 ccw(c88.259,77.475) 88.264,77.735 cw(c88.498,80.116) 86.106,80.095 ccw(c83.418,80.116) 83.439,82.804 83.693,83.058 84.074,83.058 ccw(c84.074,85.852) 86.868,85.852 cw(c88.646,85.852) 88.472,87.621 ccw(c88.428,87.84) 88.646,87.884 88.646,111.506 ccw(c88.386,111.511) 88.391,111.771 cw(c88.625,114.152) 86.233,114.131 ccw(c83.545,114.152) 83.566,116.84 ; 76.412,53.933 76.454,53.975 ; 85.217,78.486 54.356,78.486 54.356,53.975 85.344,53.975 ; 85.344,54.102 85.344,78.359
